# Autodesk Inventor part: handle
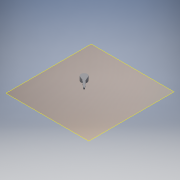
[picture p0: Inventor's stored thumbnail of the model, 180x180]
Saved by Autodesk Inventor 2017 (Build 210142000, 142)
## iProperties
Created: 2017-05
Part Number: handle
Material: Generic
Document SubType Name: Modeling
Designer: 1717440
Density: 1 g/cm^3
Appearance: Default
Author: 1717440
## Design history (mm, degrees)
workplane "Work Plane1"
sketch "Sketch1"
  geometry: C1 r 3.386 at (28.282, 83.089) reference; C2 r 3.486 at (28.282, 83.089); C3 r 5.613 at (28.282, 83.089); 1 further point
  constraints: 3 centre point, 1 coincident, 2 other
  dimensions: "d0" = 0.1 radial gap between concentric circles of C1 C2
workplane "Work Plane2"
extrude "Extrusion1" new body sketch "Sketch1" stored distance "d1" = 10; taper "d2" = 0 deg
sketch "Sketch2"
  geometry: C1 r 5.613 at (0, 0) reference; C2 r 5.613 at (0, 0); 1 further point
  constraints: 1 centre point, 1 coincident, 1 concentric
extrude "Extrusion2" join sketch "Sketch2" distance "d3" = 3; taper "d4" = 0 deg
sketch "Sketch3"
  geometry: L1 (0, 0)-(21, -21); L2 (21.601, -20.399)-(21, -21); L3 (21.601, -20.399)-(2, 2); L4 (20.399, -21.601)-(21, -21); L5 (20.399, -21.601)-(-2, -2); L6 (2, 2)-(-2, -2); C1 r 5.613 at (0, 0) reference; 1 further point
  constraints: 12 end point, 2 symmetric about line
extrude "Extrusion3" join sketch "Sketch3" distance "d5" = 2.5; taper "d6" = 0 deg
sketch "Sketch4"
  geometry: L1 (-1.431, -0.671)-(-2.771, -1.946) reference; L2 (-2.082, -2.67)-(-0.742, -1.396) reference; L3 (-0.742, -1.396)-(-1.431, -0.671) reference; L4 (-0.742, -1.396)-(-2.155, -2.74); L5 (-0.742, -1.396)-(-1.431, -0.671); L6 (-1.431, -0.671)-(-3.206, -2.359); L7 (-0.742, -1.396)-(-2.517, -3.084); L8 (-2.517, -3.084)-(-3.206, -2.359); L9 (-0.884, -1.393)-(-2.234, -2.677); L10 (-2.785, -2.097)-(-1.435, -0.813); L11 (-1.435, -0.813)-(-0.884, -1.393); A1 r 3.386 centre (0, 0) between (-2.082, -2.67) and (-2.771, -1.946) reference; A2 r 3.486 centre (0, 0) between (-2.234, -2.677) and (-2.785, -2.097); 2 further points
  constraints: 16 end point, 3 point on line, 2 point on circle, 1 centre point, 1 collinear, 1 perpendicular, 5 other
  dimensions: "d7" = 0.1 distance between parallel lines of L2 L9
extrude "Extrusion4" join sketch "Sketch4" stored distance "d8" = 2.5; taper "d9" = 0 deg
sketch "Sketch5"
  geometry: L1 (-3.344, 2.5)-(-1.7, 2.5) reference; L2 (-2.522, 2.5)-(0.769, 2.5); L3 (0.769, 2.5)-(0.769, -0.577); L4 (0.769, -0.577)-(-2.522, -0.577); L5 (-2.522, -0.577)-(-2.522, 2.5); 1 further point
  constraints: 8 end point, 2 parallel, 1 horizontal, 1 midpoint, 1 perpendicular
extrude "Extrusion5" cut sketch "Sketch5" distance "d10" = 3; taper "d11" = 0 deg
chamfer "Chamfer1" distance "d12" = 3.75; stored, may be unused: second distance "d13" = 2, angle "d14" = 45 deg
chamfer "Chamfer2" distance "d15" = 4.25; stored, may be unused: second distance "d16" = 2, angle "d17" = 45 deg
body "Solid1"
node "Reference1"
